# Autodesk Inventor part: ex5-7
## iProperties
Created: 2007-03
Part Number: ex5-7
Document SubType Name: Modeling
Designer: Elise Moss
Density: 1 g/cm^3
Mass: 233.112 g
Surface Area: 391.583 cm^2
Volume: 233.112 cm^3
Author: Elise Moss
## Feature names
1. Extrusion1
2. Hole1
3. Extrusion2
